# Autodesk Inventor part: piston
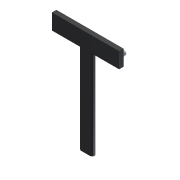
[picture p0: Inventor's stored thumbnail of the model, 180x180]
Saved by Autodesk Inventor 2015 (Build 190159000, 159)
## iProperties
Created: 2020-09
Part Number: piston
Material: 一般
Document SubType Name: Modeling
Designer: 徐冠倫
Mass: 110.47 g
Surface Area: 292.372 cm^2
Volume: 110.47 cm^3
Density: 1 g/cm^3
Appearance: 預設
Author: 徐冠倫
Author: IANNIAN
Title: D:\Desktop\OCW-Computer-Aided Engineering Drawing\OCW_Topic 06：組合圖與機構模擬(進階)\6-1_Flexibility\Mechanical Gripper(piston)\Mechanical Gripper(STP)\piston.stp
Creation Date: 2020-09-04
Sending System: Autodesk Inventor 2020
Preprocessor: ST-DEVELOPER v18
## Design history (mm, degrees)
node "piston1"
body "Solid1"
node "Base1"
